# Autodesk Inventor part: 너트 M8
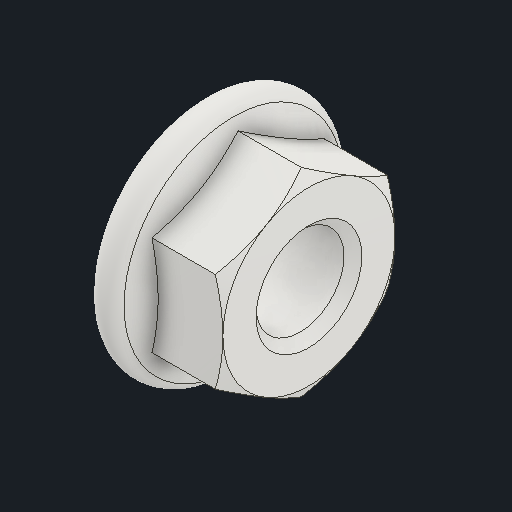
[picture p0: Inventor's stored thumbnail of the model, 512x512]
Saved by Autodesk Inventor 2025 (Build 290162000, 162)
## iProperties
Created: 2025-08
Part Number: 너트 M8
Material: 스테인리스강
Description: 플랜지붙이 6각 너트 - 일반 스레드
Document SubType Name: Modeling
Designer: infra11
Density: 8 g/cm^3
Appearance: 기본값
Author: jhkim
Sending System: Autodesk Inventor 2026
Preprocessor: ST-DEVELOPER v20.1
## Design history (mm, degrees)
feature "Solid1"
node "솔리드1"
